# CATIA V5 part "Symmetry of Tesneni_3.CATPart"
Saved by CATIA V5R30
Part number: Symmetry of Tesneni_3
Bounding box of the stored display mesh (mm): x 0 to 1.2, y -6 to 6, z -6 to 6
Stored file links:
  E:\Bakalarka\Model\Forma_v7\Symmetry of Tesneni_3.CATPart
  E:\Bakalarka\Model\Forma_v7\Tesneni.CATPart
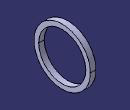
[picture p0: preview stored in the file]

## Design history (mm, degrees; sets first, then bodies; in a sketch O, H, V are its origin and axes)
Body1 (main body)
  Body2 "Body from original PartBody"
    Solid1: linked copy from another document
  Assemble1: tool Body2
